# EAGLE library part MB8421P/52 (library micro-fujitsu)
MICROCONTROLLER/MEMORY DEVICE
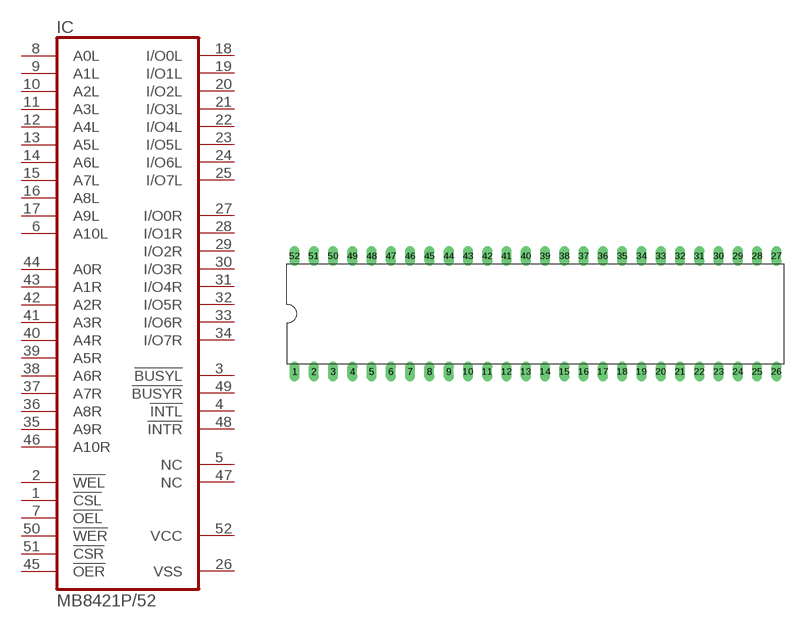
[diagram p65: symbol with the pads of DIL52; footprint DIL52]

Designator prefix IC

## MB8421P/52 (OC_FARNELL: unknown; OC_NEWARK: unknown)  [DIL52]
1  !CSL  in
2  !WEL  in
3  !BUSYL  out
4  !INTL  out
5  NC  nc
6  A10L  in
7  !OEL  in
8  A0L  in
9  A1L  in
10  A2L  in
11  A3L  in
12  A4L  in
13  A5L  in
14  A6L  in
15  A7L  in
16  A8L  in
17  A9L  in
18  I/O0L
19  I/O1L
20  I/O2L
21  I/O3L
22  I/O4L
23  I/O5L
24  I/O6L
25  I/O7L
26  VSS  pwr
27  I/O0R
28  I/O1R
29  I/O2R
30  I/O3R
31  I/O4R
32  I/O5R
33  I/O6R
34  I/O7R
35  A9R  in
36  A8R  in
37  A7R  in
38  A6R  in
39  A5R  in
40  A4R  in
41  A3R  in
42  A2R  in
43  A1R  in
44  A0R  in
45  !OER  in
46  A10R  in
47  NC  nc
48  !INTR  out
49  !BUSYR  out
50  !WER  in
51  !CSR  in
52  VCC  pwr

## Footprint DIL52 (pad centres in mm)
Dual In Line Package
drill 0.813 long: 1 -31.75,-7.62; 2 -29.21,-7.62; 3 -26.67,-7.62; 4 -24.13,-7.62; 5 -21.59,-7.62; 6 -19.05,-7.62; 7 -16.51,-7.62; 8 -13.97,-7.62; 9 -11.43,-7.62; 10 -8.89,-7.62; 11 -6.35,-7.62; 12 -3.81,-7.62; 13 -1.27,-7.62; 14 1.27,-7.62; 15 3.81,-7.62; 16 6.35,-7.62; 17 8.89,-7.62; 18 11.43,-7.62; 19 13.97,-7.62; 20 16.51,-7.62; 21 19.05,-7.62; 22 21.59,-7.62; 23 24.13,-7.62; 24 26.67,-7.62; 25 29.21,-7.62; 26 31.75,-7.62; 27 31.75,7.62; 28 29.21,7.62; 29 26.67,7.62; 30 24.13,7.62; 31 21.59,7.62; 32 19.05,7.62; 33 16.51,7.62; 34 13.97,7.62; 35 11.43,7.62; 36 8.89,7.62; 37 6.35,7.62; 38 3.81,7.62; 39 1.27,7.62; 40 -1.27,7.62; 41 -3.81,7.62; 42 -6.35,7.62; 43 -8.89,7.62; 44 -11.43,7.62; 45 -13.97,7.62; 46 -16.51,7.62; 47 -19.05,7.62; 48 -21.59,7.62; 49 -24.13,7.62; 50 -26.67,7.62; 51 -29.21,7.62; 52 -31.75,7.62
